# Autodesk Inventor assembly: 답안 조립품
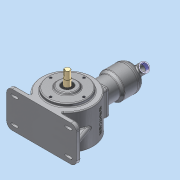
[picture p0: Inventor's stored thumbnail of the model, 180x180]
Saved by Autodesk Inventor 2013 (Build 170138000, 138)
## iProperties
Created: 2015-06
Part Number: 답안 조립품
Document SubType Name: Assembly
Designer: dgall
Author: dgall
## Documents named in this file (15)
- C:\Users\dgall\Desktop\450605V1019\답안 조립품.iam
- C:\Users\dgall\Desktop\450605V1019\1본체.ipt
- C:\Users\dgall\Desktop\450605V1019\실린더.ipt
- C:\Users\dgall\Desktop\450605V1019\실린더헤드.ipt
- C:\Users\dgall\Desktop\450605V1019\메인커버.ipt
- C:\Users\dgall\Desktop\450605V1019\메인 크랭크 축-구동부.ipt
- C:\Users\dgall\Desktop\450605V1019\크랭크 서브축.ipt
- C:\Users\dgall\Desktop\450605V1019\커넥팅 로드.ipt
- C:\Users\dgall\Desktop\450605V1019\피스톤.ipt
- C:\Users\dgall\Desktop\450605V1019\피스톤 핀.ipt
- C:\Users\dgall\Desktop\450605V1019\베어링 6204.ipt
- C:\Users\dgall\Desktop\450605V1019\베어링 NA 4902.ipt
- C:\Users\dgall\Desktop\450605V1019\오일실.ipt
- C:\Users\dgall\Desktop\450605V1019\M5x0.8.ipt
- C:\Users\dgall\Desktop\450605V1019\M4x0.7.ipt
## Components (15 placed, 5 different names)
1. 1본체:1
2. 피스톤:1
3. 피스톤 핀:1
4. M5x0.8:1
5. M5x0.8:2
6. M5x0.8:3
7. M5x0.8:4
8. M4x0.7:1
9. M4x0.7:2
10. M4x0.7:3
11. M4x0.7:4
12. M4x0.7:5
13. M4x0.7:6
14. M4x0.7:7
15. M4x0.7:8
